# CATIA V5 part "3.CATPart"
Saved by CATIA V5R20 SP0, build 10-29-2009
Part number: 3
Bounding box of the stored display mesh (mm): x -95 to 163, y -77.362 to 77.362, z -85 to 85
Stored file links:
  E:\Ehsan\Amoozesh\CATIA\CATIA Course\Advanced\Videos\Session-24\3.CATPart
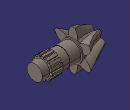
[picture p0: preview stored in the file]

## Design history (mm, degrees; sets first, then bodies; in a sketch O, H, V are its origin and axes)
AxisSystem1: origin (0, 0, 0), X (1, 0, 0), Y (0, 1, 0), Z (0, 0, 1)
Set1
  Plane1: type Offset, RefPlane YZ plane of AxisSystem1, Offset 45, reversed
  Sketch1 on Plane1, origin (-45, 0, 0), H (0, 1, 0), V (0, 0, 1)
    point P1 (0, 0)
    construction line L1 through (0, 0) direction (1, 0)
    construction line L2 through (0, 0) direction (0, 1)
    arc A1 centre (-0.0087, -0.0325) radius 37.5335 from (13.6962, 34.9094) to (5.5935, 37.0805) ccw
    arc A2 centre (-41.6557, 25.074) radius 48.7508 from (5.5935, 37.0805) to (-11.0664, 63.0336) ccw
    line L3 (-11.0664, 63.0336) -> (-21.933, 60.1219)
    arc A3 centre (23.5379, 42.5426) radius 48.7508 from (-21.933, 60.1219) to (-23.3843, 29.3159) ccw
    arc A4 centre (0.0238, -0.0238) radius 37.5335 from (-23.3843, 29.3159) to (-29.3159, 23.3843) ccw
    arc A5 centre (-42.5426, -23.5379) radius 48.7508 from (-29.3159, 23.3843) to (-60.1219, 21.933) ccw
    line L4 (-60.1219, 21.933) -> (-63.0336, 11.0664)
    arc A6 centre (-25.074, 41.6557) radius 48.7508 from (-63.0336, 11.0664) to (-37.0805, -5.5935) ccw
    arc A7 centre (0.0325, 0.0087) radius 37.5335 from (-37.0805, -5.5935) to (-34.9094, -13.6962) ccw
    arc A8 centre (-0.8869, -48.6119) radius 48.7508 from (-34.9094, -13.6962) to (-49.0555, -41.1006) ccw
    line L5 (-49.0555, -41.1006) -> (-41.1006, -49.0555)
    arc A9 centre (-48.6119, -0.8869) radius 48.7508 from (-41.1006, -49.0555) to (-13.6962, -34.9094) ccw
    arc A10 centre (0.0087, 0.0325) radius 37.5335 from (-13.6962, -34.9094) to (-5.5935, -37.0805) ccw
    arc A11 centre (41.6557, -25.074) radius 48.7508 from (-5.5935, -37.0805) to (11.0664, -63.0336) ccw
    line L6 (11.0664, -63.0336) -> (21.933, -60.1219)
    arc A12 centre (-23.5379, -42.5426) radius 48.7508 from (21.933, -60.1219) to (23.3843, -29.3159) ccw
    arc A13 centre (-0.0238, 0.0238) radius 37.5335 from (23.3843, -29.3159) to (29.3159, -23.3843) ccw
    arc A14 centre (42.5426, 23.5379) radius 48.7508 from (29.3159, -23.3843) to (60.1219, -21.933) ccw
    line L7 (60.1219, -21.933) -> (63.0336, -11.0664)
    arc A15 centre (25.074, -41.6557) radius 48.7508 from (63.0336, -11.0664) to (37.0805, 5.5935) ccw
    arc A16 centre (-0.0325, -0.0087) radius 37.5335 from (37.0805, 5.5935) to (34.9094, 13.6962) ccw
    arc A17 centre (0.8869, 48.6119) radius 48.7508 from (34.9094, 13.6962) to (49.0555, 41.1006) ccw
    line L8 (49.0555, 41.1006) -> (41.1006, 49.0555)
    arc A18 centre (48.6119, 0.8869) radius 48.7508 from (41.1006, 49.0555) to (13.6962, 34.9094) ccw
  Plane2: type Offset, RefPlane Plane1, Offset 50, reversed
  Sketch2 on Plane2, origin (-95, 0, 0), H (0, 1, 0), V (0, 0, 1)
    point P1 (0, 0)
    arc A1 centre (0, -0.0225) radius 25.0223 from (2.7962, 24.8431) to (-2.7962, 24.8431) ccw
    arc A2 centre (-31.1506, 8.9589) radius 32.5005 from (-2.7962, 24.8431) to (-18.0024, 38.6811) ccw
    line L1 (-18.0024, 38.6811) -> (-24.4976, 34.9311)
    arc A3 centre (7.8167, 31.4567) radius 32.5005 from (-24.4976, 34.9311) to (-20.1167, 14.8431) ccw
    arc A4 centre (0.0194, -0.0112) radius 25.0223 from (-20.1167, 14.8431) to (-22.9129, 10) ccw
    arc A5 centre (-23.334, -22.4978) radius 32.5005 from (-22.9129, 10) to (-42.5, 3.75) ccw
    line L2 (-42.5, 3.75) -> (-42.5, -3.75)
    arc A6 centre (-23.334, 22.4978) radius 32.5005 from (-42.5, -3.75) to (-22.9129, -10) ccw
    arc A7 centre (0.0194, 0.0112) radius 25.0223 from (-22.9129, -10) to (-20.1167, -14.8431) ccw
    arc A8 centre (7.8167, -31.4567) radius 32.5005 from (-20.1167, -14.8431) to (-24.4976, -34.9311) ccw
    line L3 (-24.4976, -34.9311) -> (-18.0024, -38.6811)
    arc A9 centre (-31.1506, -8.9589) radius 32.5005 from (-18.0024, -38.6811) to (-2.7962, -24.8431) ccw
    arc A10 centre (0, 0.0225) radius 25.0223 from (-2.7962, -24.8431) to (2.7962, -24.8431) ccw
    arc A11 centre (31.1506, -8.9589) radius 32.5005 from (2.7962, -24.8431) to (18.0024, -38.6811) ccw
    line L4 (18.0024, -38.6811) -> (24.4976, -34.9311)
    arc A12 centre (-7.8167, -31.4567) radius 32.5005 from (24.4976, -34.9311) to (20.1167, -14.8431) ccw
    arc A13 centre (-0.0194, 0.0112) radius 25.0223 from (20.1167, -14.8431) to (22.9129, -10) ccw
    arc A14 centre (23.334, 22.4978) radius 32.5005 from (22.9129, -10) to (42.5, -3.75) ccw
    line L5 (42.5, -3.75) -> (42.5, 3.75)
    arc A15 centre (23.334, -22.4978) radius 32.5005 from (42.5, 3.75) to (22.9129, 10) ccw
    arc A16 centre (-0.0194, -0.0112) radius 25.0223 from (22.9129, 10) to (20.1167, 14.8431) ccw
    arc A17 centre (-7.8167, 31.4567) radius 32.5005 from (20.1167, 14.8431) to (24.4976, 34.9311) ccw
    line L6 (24.4976, 34.9311) -> (18.0024, 38.6811)
    arc A18 centre (31.1506, 8.9589) radius 32.5005 from (18.0024, 38.6811) to (2.7962, 24.8431) ccw
  Loft1: Sections (Sketch8; Sketch1; Sketch2)
  Sketch3 on face of Loft1, origin (0, 0, 0), H (0, 1, 0), V (0, 0, 1)
    circle A1 centre (0, 0) radius 45
    radius A1 = 45
  Extrude1: Lim1 5, Lim2 0, Element1 Sketch3
  Sketch4 on face of Extrude1, origin (5, 0, 0), H (0, 1, 0), V (0, 0, 1)
    circle A1 centre (0, 0) radius 39
    radius A1 = 39
  Extrude2: Lim1 46, Lim2 0, Element1 Sketch4
  Sketch5 on face of Extrude2, origin (51, 0, 0), H (0, 1, 0), V (0, 0, 1)
    circle A1 centre (0, 0) radius 38
    radius A1 = 38
  Extrude3: Lim1 80, Lim2 0, Element1 Sketch5
  Sketch6 on face of Extrude3, origin (131, 0, 0), H (0, 1, 0), V (0, 0, 1)
    circle A1 centre (0, 0) radius 32.5
    radius A1 = 32.5
  Extrude4: Lim1 32, Lim2 0, Element1 Sketch6
  Sketch7 on face of Extrude3, origin (131, 0, 0), H (0, 1, 0), V (0, 0, 1)
    projected circle E1 centre (0, 0) radius 38 from edge [face of Extrude3 from Sketch5.A1 | face of Extrude3]
    projected arc E2 centre (0, 0) radius 38 from (5, 37.6696) to (-5, 37.6696) ccw from edge [face of Extrude3 from Sketch5.A1 | face of Extrude3]
    line L1 (-5, 43) -> (5, 43)
    point P1 (0, 43)
    point P3 (5, 43)
    line L2 (5, 43) -> (5, 37.6696)
    point P4 (5, 37.6696)
    point P5 (-5, 37.6696)
    point P6 (-5, 43)
    line L3 (-5, 43) -> (-5, 37.6696)
    length L1 = 10
    distance L1 E1 = 5
    midpoint: L1 P1
    coincidence: P1 V, P4 E1
    horizontal: L1 H
    vertical: L2 V
    symmetry: P4 P5 V, P3 P6 V, L2 L3 V
  Extrude5: Lim1 46, Lim2 0, Element1 Sketch7
  CircPattern1: of Extrude5, instances 15, angular step 24 {= 360.0*1 deg/CircPattern1.AngularNumber}, axis from face of Extrude3 from Sketch5.A1
  Add1: tool Extrude1
  Add2: tool Extrude2
  Add3: tool Extrude3
  Add4: tool CircPattern1
  Add5: tool Extrude4
Body1 (main body)
  Sketch8 on YZ plane of AxisSystem1, origin (0, 0, 0), H (0, 1, 0), V (0, 0, 1)
    arc A1 centre (0, 0) radius 50 from (29.6863, 40.2334) to (20, 45.8258) ccw
    construction line L1 (0, 56.4844) -> (0, -54.6707)
    point P1 (0, 56.4844)
    line L2 (-7.5, 85) -> (7.5, 85)
    point P3 (0, 85)
    point P4 (-7.5, 85)
    arc A2 centre (44.9945, 46.6682) radius 65 from (-7.5, 85) to (-20, 45.8258) ccw
    point P7 (-20, 45.8258)
    point P8 (20, 45.8258)
    point P9 (7.5, 85)
    arc A3 centre (-44.9945, 46.6682) radius 65 from (7.5, 85) to (20, 45.8258) cw
    arc A4 centre (-62.9132, -15.6323) radius 65 from (-69.8622, 48.9952) to (-29.6863, 40.2334) cw
    line L3 (-77.3622, 36.0048) -> (-69.8622, 48.9952)
    arc A5 centre (-17.9186, 62.3005) radius 65 from (-77.3622, 36.0048) to (-49.6863, 5.5924) ccw
    arc A6 centre (-17.9186, -62.3005) radius 65 from (-77.3622, -36.0048) to (-49.6863, -5.5924) cw
    line L4 (-69.8622, -48.9952) -> (-77.3622, -36.0048)
    arc A7 centre (-62.9132, 15.6323) radius 65 from (-69.8622, -48.9952) to (-29.6863, -40.2334) ccw
    arc A8 centre (44.9945, -46.6682) radius 65 from (-7.5, -85) to (-20, -45.8258) cw
    line L5 (7.5, -85) -> (-7.5, -85)
    arc A9 centre (-44.9945, -46.6682) radius 65 from (7.5, -85) to (20, -45.8258) ccw
    arc A10 centre (62.9132, 15.6323) radius 65 from (69.8622, -48.9952) to (29.6863, -40.2334) cw
    line L6 (77.3622, -36.0048) -> (69.8622, -48.9952)
    arc A11 centre (17.9186, -62.3005) radius 65 from (77.3622, -36.0048) to (49.6863, -5.5924) ccw
    arc A12 centre (17.9186, 62.3005) radius 65 from (77.3622, 36.0048) to (49.6863, 5.5924) cw
    line L7 (69.8622, 48.9952) -> (77.3622, 36.0048)
    arc A13 centre (62.9132, -15.6323) radius 65 from (69.8622, 48.9952) to (29.6863, 40.2334) ccw
    arc A14 centre (0, 0) radius 50 from (-20, 45.8258) to (-29.6863, 40.2334) ccw
    arc A15 centre (0, 0) radius 50 from (-49.6863, 5.5924) to (-49.6863, -5.5924) ccw
    arc A16 centre (0, 0) radius 50 from (-29.6863, -40.2334) to (-20, -45.8258) ccw
    arc A17 centre (0, 0) radius 50 from (20, -45.8258) to (29.6863, -40.2334) ccw
    arc A18 centre (0, 0) radius 50 from (49.6863, -5.5924) to (49.6863, 5.5924) ccw
    radius A1 = 50
    distance P3 H = 85
    length L2 = 15
    radius A2 = 65
    distance P7 L1 = 20
    coincidence: P1 V, P3 L1, P7 A1, A1 A14, A14 A15, A15 A16, A16 A17, A17 A18
    vertical: L1 V
    midpoint: L2 P3
    horizontal: L2 H
    symmetry: P7 P8 L1, P4 P9 L1, A2 A3 L1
